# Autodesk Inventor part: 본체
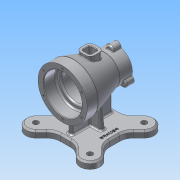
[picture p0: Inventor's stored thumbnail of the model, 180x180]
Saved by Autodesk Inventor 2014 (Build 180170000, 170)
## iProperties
Created: 2018-03
Part Number: 본체
Material: 알루미늄 6061
Document SubType Name: Modeling
Designer: user
Density: 2.71 g/cm^3
Appearance: 알루미늄 - 평지
Mass: 1015 g
Surface Area: 853.881 cm^2
Volume: 374.54 cm^3
Author: user
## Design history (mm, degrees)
sketch "스케치2"
  geometry: L1 (-9.189, -45)-(9.189, -45); L2 (45, -9.189)-(45, 9.189); L3 (9.189, 45)-(-9.189, 45); L4 (-45, 9.189)-(-45, -9.189); L5 (0, 0)-(70.711, 70.711); L6 (26.866, 52.322)-(36.77, 62.225); L7 (52.322, 26.866)-(62.225, 36.77); L8 (-52.322, 26.866)-(-62.225, 36.77); L9 (-26.866, 52.322)-(-36.77, 62.225); L10 (0, 0)-(-70.711, 70.711); L11 (-26.866, -52.322)-(-36.77, -62.225); L12 (-52.322, -26.866)-(-62.225, -36.77); L13 (0, 0)-(-70.711, -70.711); L14 (52.322, -26.866)-(62.225, -36.77); L15 (26.866, -52.322)-(36.77, -62.225); L16 (0, 0)-(70.711, -70.711); A1 r 70 centre (0, 0) between (49.497, 49.497) and (60.483, 35.239); A2 r 18 centre (49.497, 49.497) between (60.483, 35.239) and (35.239, 60.483); A3 r 18 centre (-49.497, 49.497) between (-35.239, 60.483) and (-60.483, 35.239); A4 r 18 centre (-49.497, -49.497) between (-60.483, -35.239) and (-35.239, -60.483); A5 r 18 centre (49.497, -49.497) between (35.239, -60.483) and (60.483, -35.239); A6 r 25 centre (-9.189, 70) between (-26.866, 52.322) and (-9.189, 45); A7 r 25 centre (9.189, 70) between (9.189, 45) and (26.866, 52.322); A8 r 25 centre (-70, 9.189) between (-45, 9.189) and (-52.322, 26.866); A9 r 25 centre (-70, -9.189) between (-52.322, -26.866) and (-45, -9.189); A10 r 25 centre (-9.189, -70) between (-9.189, -45) and (-26.866, -52.322); A11 r 25 centre (9.189, -70) between (26.866, -52.322) and (9.189, -45); A12 r 25 centre (70, -9.189) between (45, -9.189) and (52.322, -26.866); A13 r 25 centre (70, 9.189) between (52.322, 26.866) and (45, 9.189); 13 further points
  constraints: 37 point on circle, 32 end point, 22 point on line, 18 tangent, 13 centre point, 7 equal radius, 4 parallel, 3 coincident, 1 horizontal, 1 perpendicular, 53 other
  dimensions: "d2" = 140 diameter of A1; "d3" = 100 distance of L5.start L5.end; "d7" = 360 deg dimension on point (0, 0) L5.end (derived); "d9" = 25 radius of A6
extrude "돌출1" new body sketch "스케치2" distance "d10" = 12; taper "d11" = 0 deg
hole "구멍1" sketch "스케치2" diameter "d12" = 10; stored, may be unused: countersink angle "d16" = 90 deg, drill point angle "d18" = 118 deg; dims "d13" = 6, "d14" = 4, "d15" = 2, "d17" = 8
sketch "스케치3"
  geometry: L1 (-70.164, 82)-(77.15, 82); L2 (-26.866, 0)-(-9.189, 0) reference; L3 (0, -16.4)-(0, 98.4) reference; L4 (-50, 127)-(-50, 118); L5 (50, 109.5)-(50, 103); L6 (-50, 127)-(-30, 127); L7 (50, 109.5)-(27, 109.5); L8 (-30, 127)-(27, 109.5); L9 (-49, 117)-(-30, 117); L10 (-27, 114)-(-27, 111); L11 (-24, 108)-(17, 108); L12 (20, 105)-(20, 105); L13 (23, 102)-(49, 102); L14 (-50, 118)-(-49, 117); L15 (49, 102)-(50, 103); A1 r 3 centre (-30, 114) between (-27, 114) and (-30, 117); A2 r 3 centre (-24, 111) between (-27, 111) and (-24, 108); A3 r 3 centre (17, 105) between (20, 105) and (17, 108); A4 r 3 centre (23, 105) between (20, 105) and (23, 102); 6 further points
  constraints: 26 end point, 10 point on line, 8 point on circle, 8 tangent, 6 parallel, 4 centre point, 3 equal radius, 3 perpendicular, 1 horizontal
  dimensions: "d19" = 82 distance between parallel lines of L2 L1; "d20" = 50 distance between parallel lines of L4 L3; "d22" = 90 diameter of L6 L1; "d23" = 55 diameter of L7 L1; "d24" = 20 distance of L4.start L6.end; "d26" = 100 distance between parallel lines of L5 L4; "d27" = 77 distance from line of L7.end L4; "d28" = 23 distance of point (-50, 117) point (-27, 117); "d29" = 70 diameter of L9 L1; "d30" = 47 distance of point (-27, 108) point (20, 108); "d31" = 52 diameter of L11 L1; "d32" = 40 diameter of L13 L1; "d33" = 3 radius of A1; "d34" = 1 distance of L4.end point (-50, 117); "d35" = 1 distance of L9.start point (-50, 117) (= d34); "d36" = 1 distance of L13.end point (50, 102) (= d34); "d37" = 1 distance of L5.end point (50, 102) (= d36)
revolve "회전1" sketch "스케치3" stored, may be unused: angle "d38" = 90 deg
sketch "스케치4"
  geometry: L1 (-37, 4)-(37, 4); L2 (37, 4)-(37, -4); L3 (37, -4)-(-37, -4); L4 (-37, -4)-(-37, 4); L5 (-37, 4)-(37, -4); L6 (37, 4)-(-37, -4); 1 further point
  constraints: 12 end point, 2 midpoint, 2 parallel, 1 horizontal, 1 perpendicular
  dimensions: "d39" = 74 distance of L2.end L3.end; "d40" = 8 distance of L1.end L2.end
extrude "돌출2" join sketch "스케치4" stored distance "d41" = 12; taper "d42" = 0 deg
sketch "스케치5"
  geometry: L1 (-9.189, 0)-(-9.189, 12) reference; L2 (-26.866, 12)-(-9.189, 12) reference; L3 (9.189, 12)-(-9.189, 12) reference; L4 (26.866, 0)-(9.189, 0) reference; L5 (9.189, 0)-(9.189, 12) reference; L6 (26.866, 12)-(9.189, 12) reference; L7 (26.866, 0)-(26.866, 12) reference; L8 (-20.376, 53.428)-(-24, 12); L9 (-24, 12)-(0, 12); L10 (-20.376, 53.428)-(20.376, 53.428); L11 (0, 152.4)-(0, -25.4) reference; L12 (20.376, 53.428)-(24, 12); L13 (24, 12)-(0, 12); 1 further point
  constraints: 10 end point, 2 symmetric about line, 1 midpoint, 1 parallel, 1 point on line
  dimensions: "d43" = 24 horizontal distance of point (0, 0) L8.end; "d44" = 95 deg angle of L2 L8; "d102" = 24 distance of L12.end L9.end (derived)
extrude "돌출3" join sketch "스케치5" stored distance "d45" = 8; taper "d46" = 0 deg
node "작업 평면1"
sketch "스케치6"
  geometry: L1 (50, 45)-(50, -45) reference; L2 (-50, 27.5)-(-50, -27.5) reference; L3 (-12.5, -12.5)-(12.5, -12.5); L4 (12.5, -12.5)-(12.5, 12.5); L5 (12.5, 12.5)-(-12.5, 12.5); L6 (-12.5, 12.5)-(-12.5, -12.5); L7 (-12.5, -12.5)-(12.5, 12.5); L8 (12.5, -12.5)-(-12.5, 12.5); L9 (-7.5, -7.5)-(7.5, -7.5); L10 (7.5, -7.5)-(7.5, 7.5); L11 (7.5, 7.5)-(-7.5, 7.5); L12 (-7.5, 7.5)-(-7.5, -7.5); L13 (-7.5, -7.5)-(7.5, 7.5); L14 (7.5, -7.5)-(-7.5, 7.5); 2 further points
  constraints: 24 end point, 6 midpoint, 4 parallel, 2 horizontal, 2 perpendicular
  dimensions: "d48" = 50 distance from line of L2 point (0, 0) (derived); "d49" = 50 distance from line of L1 point (0, 0) (derived); "d50" = 25 distance of L5.end L4.end; "d51" = 25 distance of L4.end L3.end; "d52" = 15 distance of L11.end L10.end; "d53" = 15 distance of L10.end L9.end
extrude "돌출4" join sketch "스케치6" stored distance "d54" = 8; taper "d55" = 0 deg
extrude "돌출5" cut sketch "스케치6" stored distance "d56" = 8; taper "d57" = 0 deg
sketch "스케치7"
  geometry: L1 (-107.4, 0)-(70.4, 0) reference; C1 r 27.5 at (0, 0) reference; C2 r 21 at (0, 0) reference; A1 r 27.5 centre (0, 0) between (26.609, -6.943) and (26.609, 6.943); A2 r 7 centre (27.5, 0) between (26.609, -6.943) and (26.609, 6.943); A3 r 27.5 centre (0, 0) between (26.609, -6.943) and (26.609, 6.943); 1 further point
  constraints: 7 point on circle, 3 centre point, 2 coincident, 1 point on line
  dimensions: "d59" = 14 diameter of A2; "d60" = 27.5 distance of C1.centre A2.centre
extrude "돌출6" join sketch "스케치7" distance "d61" = 15; taper "d62" = 0 deg
sketch "스케치8"
  geometry: A1 r 7 centre (0, 0) between (-0.891, -6.943) and (-0.891, 6.943) reference; 2 further points
  constraints: 1 coincident
hole "구멍2" sketch "스케치8" at (0, 0) diameter "d63" = 3.242; stored, may be unused: countersink angle "d67" = 90 deg, drill point angle "d69" = 118 deg; dims "d64" = 9, "d65" = 4, "d66" = 2, "d68" = 11
sketch "스케치9"
  geometry: C1 r 36 at (0, 0) reference; 2 further points
  dimensions: "d73" = 40 distance of C1.centre point (-40, 0)
hole "구멍3" sketch "스케치9" at (-40, 0) diameter "d74" = 3.242; stored, may be unused: countersink angle "d78" = 90 deg, drill point angle "d80" = 118 deg; dims "d75" = 9, "d76" = 4, "d77" = 2, "d79" = 11
fillet "모깎기1" dims "d84" = 8
fillet "모깎기2" dims "d85" = 3
fillet "모깎기3" dims "d86" = 1
fillet "모깎기4" dims "d87" = 3
fillet "모깎기5" dims "d88" = 1
chamfer "모따기1" distance "d89" = 3; stored, may be unused: second distance "d90" = 2, angle "d91" = 45 deg
fillet "모깎기6" dims "d92" = 3
fillet "모깎기7" dims "d93" = 3
fillet "모깎기8" dims "d94" = 3
sketch "스케치10"
  geometry: L1 (-45, 9.189)-(-45, -9.189) reference; 2 further points
  constraints: 1 other
  dimensions: "d95" = 35 distance of point (0, 35) point (0, 0); "d96" = 45 distance from line of point (0, 35) L1
feature "엠보싱1" sketch "스케치10" dims "d97" = 0.5, "d98" = 0
chamfer "모따기2" distance "d99" = 1; stored, may be unused: second distance "d100" = 2, angle "d101" = 45 deg
node "솔리드1"
pattern_circular "원형 패턴1" dims angle "d71" = 360 deg
pattern_circular "원형 패턴2" dims angle "d82" = 360 deg
node "투영된 루프1"
other parameters: "d4" = 36, "d47" = 127
